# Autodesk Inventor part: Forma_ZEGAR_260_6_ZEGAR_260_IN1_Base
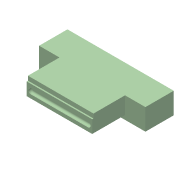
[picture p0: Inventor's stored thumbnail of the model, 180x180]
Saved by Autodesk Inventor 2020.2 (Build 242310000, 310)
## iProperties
Created: 2015-01
Part Number: Forma_ZEGAR_260_6_ZEGAR_260_IN1_Base
Material: Ogólny
Document SubType Name: Modeling
Designer: F.Stasiak
Density: 1 g/cm^3
Appearance: Domyślna
Catalog Web Link: www.expertbooks.pl
Manager: www.cadconsulting.pl
Company: Fabian Stasiak CAD Consulting
Author: F.Stasiak
Subject: Zbiór ćwiczeń. Autodesk Inventor 2020. Kurs Professional
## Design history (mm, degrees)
node "Forma_ZEGAR_260_4_ZEGAR_260_MP"
feature "Bryła5::Forma_ZEGAR_260_4_ZEGAR_260_MP"
tag "Bryła wyprowadzona1"
node "Bryła1"
feature "Forma_ZEGAR_260_4_ZEGAR_260_MP_Bodies"
